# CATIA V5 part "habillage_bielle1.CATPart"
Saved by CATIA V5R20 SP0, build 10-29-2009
Part number: habillage_bielle1
Bounding box of the stored display mesh (mm): x 90 to 100, y -360 to -340, z -60 to 10
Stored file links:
  C:\Users\Noëllie\Documents\IFMA\2A\S3\IAO\Projet Artobolevski\Catia\habillage_bielle1.CATPart
  C:\Users\Noëllie\Documents\IFMA\2A\S3\IAO\Projet Artobolevski\Catia\assemblage_balance.CATProduct
  C:\Users\Noëllie\Documents\IFMA\2A\S3\IAO\Projet Artobolevski\Catia\habillage_support1.CATPart
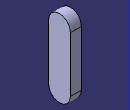
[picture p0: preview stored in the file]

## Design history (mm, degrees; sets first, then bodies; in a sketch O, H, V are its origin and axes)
Set1
  Plane1 "Plan_base1": linked copy from another document
  Point1 "C1": linked copy from another document
  Point2 "B1g": linked copy from another document
Body1 (main body)
  Sketch1 on Plane1, origin (100, 0, 0), H (0, 1, 0), V (0, 0, 1)
    line L1 (-360, 0) -> (-360, -50)
    point P1 (-360, 0)
    line L2 (-340, 0) -> (-340, -50)
    arc A1 centre (-350, 0) radius 10 from (-360, 0) to (-340, 0) cw
    point P5 (-350, 0)
    arc A2 centre (-350, -50) radius 10 from (-360, -50) to (-340, -50) ccw
    point P6 (-350, -50)
    reference projected point E1 (-350, -50) from Point1
    reference projected point E2 (-350, 0) from Point2
    distance L1 L2 = 20
    coincidence: P1 H, P6 E1, P5 E2
    vertical: L1 V, L2 V
    tangency: A1 L2, A2 L2
  Pad1: profile Sketch1, direction (1, 0, 0), length 0, opposite side length 10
